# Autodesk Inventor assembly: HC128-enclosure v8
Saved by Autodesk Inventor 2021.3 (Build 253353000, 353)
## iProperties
Created: 2022-07
Part Number: HC128-enclosure v8
Document SubType Name: Assembly
Designer: Administrator
Title: HC128-enclosure v8 v1
Author: Administrator
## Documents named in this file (5)
- c:\worker\convert-fusion-r04\tmp\job-1\186\output\files\05ef811f-4573-476e-8ba5-de3f58aa0f0a\3787bbb2-3703-4db3-a357-50c61a1c7dc7.iam
- c:\worker\convert-fusion-r04\tmp\job-1\186\output\files\05ef811f-4573-476e-8ba5-de3f58aa0f0a\body.iam
- c:\worker\convert-fusion-r04\tmp\job-1\186\output\files\05ef811f-4573-476e-8ba5-de3f58aa0f0a\Nanodrive v1.iam
- c:\worker\convert-fusion-r04\tmp\job-1\186\output\files\05ef811f-4573-476e-8ba5-de3f58aa0f0a\Double-mini-amp v5.iam
- c:\worker\convert-fusion-r04\tmp\job-1\186\output\files\05ef811f-4573-476e-8ba5-de3f58aa0f0a\Foot.ipt
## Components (4 placed, 4 different names)
1. body:1 [sub-assembly]
2. Nanodrive v1:1 [sub-assembly]
3. Double-mini-amp v5:1 [sub-assembly]
4. Foot:1
